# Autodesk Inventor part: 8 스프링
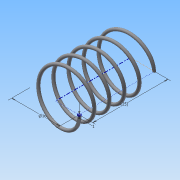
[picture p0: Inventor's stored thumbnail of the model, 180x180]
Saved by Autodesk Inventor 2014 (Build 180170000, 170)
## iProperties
Created: 2015-06
Part Number: 8 스프링
Material: 강철, 연강
Document SubType Name: Modeling
Designer: Administrator
Density: 7.86 g/cm^3
Appearance: 강철
Mass: 1.53535 g
Surface Area: 7.89042 cm^2
Volume: 0.195337 cm^3
Author: Administrator
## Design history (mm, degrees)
sketch "스케치1"
  geometry: L1 (0, 0)-(8, 0); L2 (8, 0)-(8, 21.5); L3 (8, 21.5)-(0, 21.5); L4 (0, 21.5)-(0, 0); C1 r 0.5 at (8, 0)
  constraints: 8 end point, 2 parallel, 1 centre point, 1 coincident, 1 horizontal, 1 perpendicular
  dimensions: "d0" = 16 diameter of L2 L4; "d1" = 21.5 distance of L1.end L2.end (derived); "d2" = 1 diameter of C1
feature "코일1" sketch "스케치1" pitch "d3" = 10; turns "d5" = 5; dims "d4" = 21.5 (= d1), "d6" = 0, angle "d7" = 90 deg, angle "d8" = 90 deg, "d9" = 0, "d10" = 0
sketch "스케치2"
  geometry: L1 (-8.5, 0)-(-7.5, 0) reference; 1 further point
  constraints: 1 horizontal alignment
extrude "돌출1" cut sketch "스케치2" stored distance "d11" = 10; taper "d12" = 0 deg
node "작업 평면1"
sketch "스케치3"
  geometry: L1 (8.5, 0)-(7.5, 0) reference; 1 further point
  constraints: 1 horizontal alignment
extrude "돌출2" cut sketch "스케치3" stored distance "d14" = 10; taper "d15" = 0 deg
node "솔리드1"
node "절단 모서리 투영1"
node "절단 모서리 투영2"
other parameters: "d13" = -21.5 (= -d1)
